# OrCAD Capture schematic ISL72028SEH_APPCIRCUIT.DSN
size A
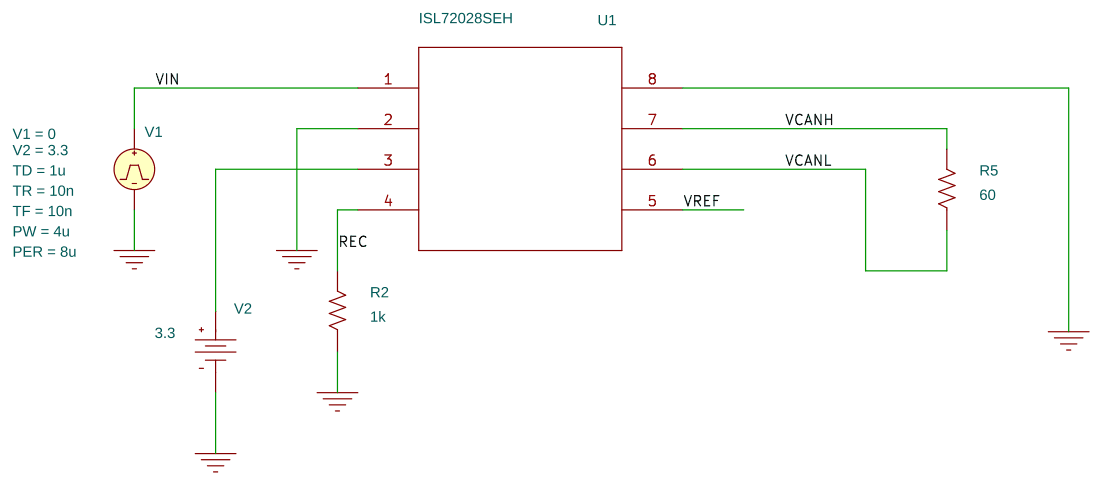
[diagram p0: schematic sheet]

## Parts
R2  1k  [AX/RC05]
R5  60  [AX/RC05]
U1  ISL72028SEH
V1  VPULSE
V2  VDC

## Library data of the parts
R2 R5 = R
U1 = ISL72027SEH: PspiceTemplate: X^@REFDES %CANH %CANL %D %GND %R %RS %VCC %VREF @MODEL
V1 = VPULSE: PER: 8u; PW: 4u; TD: 1u; TF: 10n; TR: 10n; V1: 0; V2: 3.3
V2 = VDC: DC: 3.3

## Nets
VIN: U1.1(D) V1.1(+)
0: R2.1 U1.2(GND) U1.8(RS) V1.2(-) V2.1(-)
REC: R2.2 U1.4(R)
VCANH: R5.2 U1.7(CANH)
VCANL: R5.1 U1.6(CANL)
VREF: U1.5(VREF)
N53151: U1.3(VCC) V2.0(+)
